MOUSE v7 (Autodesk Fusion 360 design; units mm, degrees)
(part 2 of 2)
sketch "Sketch19" plane through (0, 504.0642, 0) normal (0, 1, 0) x axis (-1, 0, 0)
  line L1 (379.7, -222.5) -> (379.7, -52.5)
  line L2 (399.8913, -222.5) -> (379.7, -222.5)
  line L3 (399.8913, -52.5) -> (399.8913, -222.5)
  line L4 (399.8913, -137.5) -> (379.7, -137.5)
  line L5 (389.7956, -133.5) -> (389.7956, -137.5)
  line L6 (389.7956, -141.5) -> (389.7956, -137.5)
  line L7 (389.7956, -149.5) -> (389.7956, -141.5)
  line L8 (389.7956, -157.5) -> (389.7956, -149.5)
  line L9 (389.7956, -165.5) -> (389.7956, -157.5)
  line L10 (389.7956, -173.5) -> (389.7956, -165.5)
  line L11 (389.7956, -181.5) -> (389.7956, -173.5)
  line L12 (389.7956, -189.5) -> (389.7956, -181.5)
  line L13 (389.7956, -197.5) -> (389.7956, -189.5)
  line L14 (389.7956, -205.5) -> (389.7956, -197.5)
  line L15 (389.7956, -213.5) -> (389.7956, -205.5)
  circle C1 centre (389.7956, -133.5) radius 2.65
  circle C2 centre (389.7956, -141.5) radius 2.5
  circle C3 centre (389.7956, -125.5) radius 2.65
  circle C4 centre (389.7956, -117.5) radius 2.65
  circle C5 centre (389.7956, -149.5) radius 2.65
  circle C6 centre (389.7956, -157.5) radius 2.65
  circle C7 centre (389.7956, -165.5) radius 2.65
  circle C8 centre (389.7956, -173.5) radius 2.65
  circle C9 centre (389.7956, -181.5) radius 2.65
  circle C10 centre (389.7956, -189.5) radius 2.65
  circle C11 centre (389.7956, -197.5) radius 2.65
  circle C12 centre (389.7956, -205.5) radius 2.65
  circle C13 centre (389.7956, -213.5) radius 2.65
  circle C14 centre (389.7956, -109.5) radius 2.65
  circle C15 centre (389.7956, -101.5) radius 2.65
  circle C16 centre (389.7956, -93.5) radius 2.65
  circle C17 centre (389.7956, -85.5) radius 2.65
  circle C18 centre (389.7956, -77.5) radius 2.65
  circle C19 centre (389.7956, -69.5) radius 2.65
  circle C20 centre (389.7956, -61.5) radius 2.65
  point P6 (379.7, -137.5)
  point P7 (399.8913, -137.5)
  point P8 (389.7956, -137.5)
  point P9 (389.7956, -133.5)
  point P10 (389.7956, -133.5)
  point P11 (389.7956, -141.5)
  point P12 (389.7956, -141.5)
  point P15 (389.7956, -141.5)
  point P16 (389.7956, -149.5)
  point P17 (389.7956, -149.5)
  point P18 (389.7956, -149.5)
  point P19 (389.7956, -157.5)
  point P20 (389.7956, -157.5)
  point P21 (389.7956, -165.5)
  point P22 (389.7956, -165.5)
  point P23 (389.7956, -165.5)
  point P24 (389.7956, -173.5)
  point P25 (389.7956, -173.5)
  point P26 (389.7956, -173.5)
  point P27 (389.7956, -181.5)
  point P28 (389.7956, -181.5)
  point P29 (389.7956, -181.5)
  point P30 (389.7956, -189.5)
  point P31 (389.7956, -189.5)
  point P32 (389.7956, -189.5)
  point P33 (389.7956, -197.5)
  point P34 (389.7956, -197.5)
  point P35 (389.7956, -197.5)
  point P36 (389.7956, -205.5)
  point P37 (389.7956, -205.5)
  point P38 (389.7956, -205.5)
  point P39 (389.7956, -213.5)
  point P40 (389.7956, -213.5)
  point P13 (389.7956, -125.5)
  point P14 (389.7956, -117.5)
  point P41 (389.7956, -109.5)
  point P42 (389.7956, -101.5)
  point P43 (389.7956, -93.5)
  point P44 (389.7956, -85.5)
  point P45 (389.7956, -77.5)
  point P46 (389.7956, -69.5)
  point P47 (389.7956, -61.5)
  midpoint L1 P6
  midpoint L3 P7
  midpoint L4 P8
  perpendicular L4 L5
  coincident P9 P10
  perpendicular L4 L6
  coincident P11 P12
  coincident P12 P15
  parallel L6 L7
  coincident P16 P17
  coincident P17 P18
  parallel L7 L8
  coincident P19 P20
  parallel L8 L9
  coincident P21 P22
  coincident P22 P23
  parallel L9 L10
  coincident P24 P25
  coincident P25 P26
  parallel L10 L11
  coincident P27 P28
  coincident P28 P29
  parallel L11 L12
  coincident P30 P31
  coincident P31 P32
  parallel L12 L13
  coincident P33 P34
  coincident P34 P35
  parallel L13 L14
  coincident P36 P37
  coincident P37 P38
  parallel L14 L15
  coincident P39 P40
  dimension "d274" distance P8 P9 = 4
  dimension "d275" diameter C1 = 5.3
  dimension "d276" distance P8 P11 = 4
  dimension "d277" diameter C2 = 5
  dimension "d278" distance P10 P13 = 8
  dimension "d279" diameter C3 = 5.3
  dimension "d280" distance P13 P14 = 8
  dimension "d281" diameter C4 = 5.3
  dimension "d282" distance P15 P16 = 8
  dimension "d283" diameter C5 = 5.3
  dimension "d284" distance P18 P19 = 8
  dimension "d285" diameter C6 = 5.3
  dimension "d286" distance P19 P21 = 8
  dimension "d287" diameter C7 = 5.3
  dimension "d288" distance P23 P24 = 8
  dimension "d289" diameter C8 = 5.3
  dimension "d290" distance P26 P27 = 8
  dimension "d291" diameter C9 = 5.3
  dimension "d292" distance P29 P30 = 8
  dimension "d293" diameter C10 = 5.3
  dimension "d294" distance P32 P33 = 8
  dimension "d295" diameter C11 = 5.3
  dimension "d296" distance P35 P36 = 8
  dimension "d297" diameter C12 = 5.3
  dimension "d298" distance P38 P39 = 8
  dimension "d299" diameter C13 = 5.3
  dimension "d300" distance P14 P41 = 8
  dimension "d301" diameter C14 = 5.3
  dimension "d302" distance P41 P42 = 8
  dimension "d303" diameter C15 = 5.3
  dimension "d304" distance P42 P43 = 8
  dimension "d305" diameter C16 = 5.3
  dimension "d306" distance P43 P44 = 8
  dimension "d307" diameter C17 = 5.3
  dimension "d308" distance P44 P45 = 8
  dimension "d309" diameter C18 = 5.3
  dimension "d310" distance P45 P46 = 8
  dimension "d311" diameter C19 = 5.3
  dimension "d312" distance P46 P47 = 8
  dimension "d313" diameter C20 = 5.3
extrude "Extrude8" add of existing geometry blind 10
extrude "Extrude9" add of existing geometry blind 10
sketch "Sketch20" plane through (0, 504.0642, 0) normal (0, 1, 0) x axis (-1, 0, 0)
  line L1 (379.7, -232.5) -> (379.7, -42.5)
  line L2 (399.8913, -232.5) -> (379.7, -232.5)
  line L3 (399.8913, -42.5) -> (399.8913, -232.5)
  line L4 (379.7, -42.5) -> (399.8913, -42.5)
  line L5 (389.7958, -45.4999) -> (389.7958, -53.4999)
  line L6 (389.795, -221.5) -> (389.795, -213.5)
  line L7 (389.795, -229.5) -> (389.795, -221.5)
  circle C1 centre (389.7958, -53.4999) radius 2.65
  circle C2 centre (389.7958, -45.4999) radius 2.65
  circle C3 centre (389.795, -221.5) radius 2.65
  circle C4 centre (389.795, -229.5) radius 2.65
  point P6 (389.7958, -53.4999)
  point P7 (389.7958, -53.4999)
  point P8 (389.7958, -45.4999)
  point P9 (389.7958, -45.4999)
  point P11 (389.795, -221.5)
  point P12 (389.795, -221.5)
  point P13 (389.795, -221.5)
  point P14 (389.795, -229.5)
  point P15 (389.795, -229.5)
  point P10 (389.795, -213.5)
  coincident P6 P7
  vertical L5
  coincident P8 P9
  vertical L6
  coincident P11 P12
  coincident P12 P13
  parallel L6 L7
  coincident P14 P15
  dimension "d319" diameter C1 = 5.3
  dimension "d320" distance P7 P8 = 8
  dimension "d321" diameter C2 = 5.3
  dimension "d322" distance P10 P11 = 8
  dimension "d323" diameter C3 = 5.3
  dimension "d324" distance P13 P14 = 8
  dimension "d325" diameter C4 = 5.3
extrude "Extrude10" cut sketch "Sketch19" + "Sketch20" profile of S1:L6 S1:C2 S1:L7 S1:C5 S1:L8 S1:C6 S1:L9 S1:C7 S1:L10 S1:C8 S1:L11 S1:C9 S1:L12 S1:C10 S1:L13 S1:C11 S1:L14 S1:C12 S1:L15 S1:C13 S2:L6 S2:C3 S2:L7 S2:C4 blind -20
extrude "Extrude11" cut of existing geometry blind -32
extrude "Extrude12" add of existing geometry blind 2
extrude "Extrude13" cut of existing geometry blind -30
work_plane "WorkPlane8" AlongDistance -97
sketch "Sketch21" plane through (0, 504.0642, 0) normal (0, 1, 0) x axis (-1, 0, 0)
  line L1 (379.7, -234.5) -> (379.7, -42.5)
  line L2 (399.8913, -234.5) -> (379.7, -234.5)
  line L3 (399.8913, -42.5) -> (399.8913, -234.5)
  line L4 (379.7, -42.5) -> (399.8913, -42.5)
  line L5 (389.7956, -137.5) -> (389.7956, -234.5)
  circle C1 centre (389.795, -229.5) radius 2.65
  circle C2 centre (389.7956, -157.5) radius 2.65
  circle C3 centre (389.7956, -189.5) radius 2.65
  circle C4 centre (389.7956, -213.5) radius 2.65
  circle C5 centre (389.7956, -181.5) radius 2.65
  circle C6 centre (389.7956, -149.5) radius 2.65
  circle C7 centre (389.7956, -165.5) radius 2.65
  circle C8 centre (389.7956, -197.5) radius 2.65
  circle C9 centre (389.7956, -205.5) radius 2.65
  circle C10 centre (389.7956, -173.5) radius 2.65
  circle C11 centre (389.7956, -141.5) radius 2.5
  circle C12 centre (389.795, -221.5) radius 2.65
  point P18 (389.7956, -234.5)
  point P19 (389.7956, -137.5)
  midpoint L2 P18
  perpendicular L2 L5
  dimension "d335" distance P18 P19 = 97
extrude "Extrude14" cut sketch "Sketch20" profile of C1 L5 C2 against normal blind 40
extrude "Extrude15" cut sketch "Sketch19" profile of C1 C3 C4 C14 C15 C16 C17 C18 C19 C20 against normal blind 25
extrude "Extrude16" add of existing geometry blind 1
extrude "Extrude17" cut of existing geometry blind -1
extrude "Extrude18" cut of existing geometry blind -7
extrude "Extrude19" cut of existing geometry blind -0.5
extrude "Extrude20" cut of existing geometry blind -7
extrude "Extrude21" cut of existing geometry blind -0.5
extrude "Extrude22" cut of existing geometry blind -5.5
sketch "Sketch13" plane through (0, 0, -202.5) normal (0, 0, -1) x axis (-1, 0, 0)
  line L1 (379.7049, 476.0642) -> (379.7049, 492.0642)
  line L2 (399.8912, 476.0642) -> (379.7049, 476.0642)
  line L3 (399.8912, 499.0642) -> (399.8912, 476.0642)
  line L4 (379.7, 499.0642) -> (399.8912, 499.0642)
  line L5 (379.7, 492.0642) -> (379.7, 499.0642)
  line L6 (379.7049, 492.0642) -> (379.7, 492.0642)
  line L7 (399.8912, 519.0178) -> (379.7, 519.0178)
  line L8 (399.8912, 517.2951) -> (399.8912, 519.0178)
  line L9 (379.7, 517.2951) -> (399.8912, 517.2951)
  line L10 (379.7, 519.0178) -> (379.7, 517.2951)
  point P10 (399.8912, 517.2951)
  point P8 (379.7, 519.0178)
  horizontal L7
  vertical L8
  horizontal L9
  vertical L10
  coincident L3 P10
  coincident L5 P8
extrude "Extrude28" add sketch "Sketch13" profile of L3 L5 L7 L8 L9 L10 along normal blind 32
sketch "Sketch14" plane through (0, 0, -72.5) normal (0, 0, 1) x axis (1, 0, 0)
  line L1 (-399.8912, 476.0642) -> (-399.8912, 499.0642)
  line L2 (-379.7049, 476.0642) -> (-399.8912, 476.0642)
  line L3 (-379.7049, 492.0642) -> (-379.7049, 476.0642)
  line L4 (-379.7, 492.0642) -> (-379.7049, 492.0642)
  line L5 (-379.7, 499.0642) -> (-379.7, 492.0642)
  line L6 (-399.8912, 499.0642) -> (-379.7, 499.0642)
  line L7 (-399.891, 519.0174) -> (-379.7, 519.0174)
  line L8 (-399.891, 516.2174) -> (-399.891, 519.0174)
  line L9 (-379.7, 516.2174) -> (-399.891, 516.2174)
  line L10 (-379.7, 519.0174) -> (-379.7, 516.2174)
  point P8 (-379.7, 519.0174)
  point P9 (-399.891, 519.0174)
  point P11 (-379.7, 516.2174)
  horizontal L7
  vertical L8
  horizontal L9
  vertical L10
  coincident L5 P8
  dimension "d356" distance P8 P9 = 20.191
  dimension "d357" distance P8 P11 = 2.8
extrude "Extrude29" add sketch "Sketch14" profile of L3 L4 L5 L7 L8 L9 L10 along normal blind 31
extrude "Extrude30" add of existing geometry blind 1.1
chamfer "Chamfer3" distance 5 Rotate Angle 80
chamfer "Chamfer4" distance 5 Rotate Angle 80
sketch "Sketch22" plane through (0, 476.0642, 0) normal (0, 1, 0) x axis (-1, 0, 0)
  line L1 (379.7049, -72.5) -> (379.7049, -100)
  line L2 (399.8912, -72.5) -> (379.7049, -72.5)
  line L3 (399.8912, -100) -> (399.8912, -72.5)
  line L4 (379.7049, -100) -> (399.8912, -100)
  line L5 (18.1656, -50) -> (430.5782, -50)
  line L6 (430.5782, -225) -> (18.1656, -225)
  line L7 (430.5782, -50) -> (430.5782, -225)
  line L8 (379.7049, -175) -> (379.7049, -202.5)
  line L9 (399.8912, -175) -> (379.7049, -175)
  line L10 (399.8912, -202.5) -> (399.8912, -175)
  line L11 (379.7049, -202.5) -> (399.8912, -202.5)
  line L12 (380, -137.5) -> (0, -137.5)
  line L13 (18.1656, -225) -> (18.1656, -50)
  circle C1 centre (190, -137.5) radius 11.2
  point P16 (190, -137.5)
  midpoint L12 P16
  dimension "d366" diameter C1 = 22.4
extrude "Extrude31" cut sketch "Sketch22" profile of L12 C1 against normal blind 30
move "Move1"
move "Move2"
work_plane "WorkPlane9" AlongDistance -20
work_plane "WorkPlane10" AlongDistance -20
sketch "Sketch23" plane through (0, 201.0642, 0) normal (0, -1, 0) x axis (-1, 0, 0)
  line L1 (-100, -75) -> (550, -75)
  line L2 (-100, 350) -> (-100, -75)
  line L3 (550, 350) -> (-100, 350)
  line L4 (550, -75) -> (550, 350)
  line L5 (225, 350) -> (225, -75)
  line L6 (550, 137.5) -> (-100, 137.5)
  line L7 (532.3496, 332.2603) -> (-82.3496, -57.2603)
  line L8 (-82.3496, 332.2603) -> (532.3496, -57.2603)
  line L9 (550, -75) -> (-100, -75)
  line L10 (550, 350) -> (550, -75)
  line L11 (-100, 350) -> (550, 350)
  line L12 (-100, -75) -> (-100, 350)
  line L13 (550, 350) -> (-100, -75)
  line L14 (-100, 350) -> (550, -75)
  line L15 (532.3496, 332.2603) -> (-82.3496, -57.2603)
  line L16 (-82.3496, 332.2603) -> (532.3496, -57.2603)
  line L17 (-89.6979, 343.264) -> (539.6979, 343.264)
  line L18 (-89.6979, -68.264) -> (-89.6979, 343.264)
  line L19 (539.6979, -68.264) -> (-89.6979, -68.264)
  line L20 (539.6979, 343.264) -> (539.6979, -68.264)
  line L21 (-89.6979, -68.264) -> (539.6979, 343.264)
  line L22 (539.6979, -68.264) -> (-89.6979, 343.264)
  point P6 (225, -75)
  point P7 (225, 350)
  point P8 (-100, 137.5)
  point P9 (550, 137.5)
  point P14 (225, 137.5)
  point P18 (225, 137.5)
  point P22 (225, 137.5)
  point P27 (225, 137.5)
  point P23 (539.6979, 343.264)
  horizontal L1
  perpendicular L1 L2
  perpendicular L2 L3
  perpendicular L1 L4
  midpoint L1 P6
  midpoint L3 P7
  midpoint L2 P8
  midpoint L4 P9
  coincident L7 P14
  coincident L8 P14
  midpoint L5 P14
  horizontal L9
  perpendicular L9 L10
  parallel L9 L11
  parallel L10 L12
  coincident L13 P18
  coincident L14 P18
  coincident P14 P18
  coincident L15 P22
  coincident L16 P22
  coincident P14 P22
  horizontal L17
  perpendicular L17 L18
  parallel L17 L19
  parallel L18 L20
  coincident L21 P27
  coincident L22 P27
  coincident L13 P23
  coincident P22 P27
extrude "Extrude32" cut sketch "Sketch23" profile of L1 L2 L3 L4 L5 L6 L9 L10 L11 L12 L17 L18 L19 L20 against normal blind 75
fillet "Fillet2" radius 27
fillet "Fillet3" radius 27
fillet "Fillet4" radius 30
fillet "Fillet5" radius 30
sketch "Sketch24" plane through (0, 168.5642, 0) normal (0, 1, 0) x axis (-1, 0, 0)
  line L1 (546, -350.953) -> (-96, -350.953)
  line L2 (550, 70.047) -> (550, -346.953)
  line L3 (-96, 74.047) -> (546, 74.047)
  line L4 (-100, -346.953) -> (-100, 70.047)
  line L5 (-62.5, 36.547) -> (-62.5, -313.453)
  line L6 (512.5, 36.547) -> (-62.5, 36.547)
  line L7 (512.5, -313.453) -> (512.5, 36.547)
  line L8 (-62.5, -313.453) -> (512.5, -313.453)
  arc A1 centre (530.6642, -331.6172) radius 7.5 clockwise from (525.5655, -337.1175) to (536.3487, -326.7247)
  arc A2 centre (531.25, -332.225) radius 7.5 clockwise from (525.5655, -337.1175) to (536.3487, -326.7247)
  arc A3 centre (-81.25, -332.225) radius 7.5 clockwise from (-86.3488, -326.7248) to (-75.5655, -337.1174)
  arc A4 centre (-80.6642, -331.6172) radius 7.5 clockwise from (-86.3488, -326.7248) to (-75.5655, -337.1174)
  arc A5 centre (-81.25, 55.25) radius 7.5 clockwise from (-75.8871, 60.4931) to (-86.0271, 49.4682)
  arc A6 centre (-80.6642, 54.7112) radius 7.5 clockwise from (-75.8871, 60.4931) to (-86.0271, 49.4682)
  arc A7 centre (-96, -346.953) radius 4 clockwise from (-96, -350.953) to (-100, -346.953)
  arc A8 centre (546, -346.953) radius 4 clockwise from (550, -346.953) to (546, -350.953)
  arc A9 centre (546, 70.047) radius 4 clockwise from (546, 74.047) to (550, 70.047)
  arc A10 centre (-96, 70.047) radius 4 clockwise from (-100, 70.047) to (-96, 74.047)
  arc A11 centre (530.6642, 54.7112) radius 7.5 clockwise from (536.0271, 49.4681) to (525.8872, 60.4931)
  arc A12 centre (531.25, 55.25) radius 7.5 clockwise from (536.0271, 49.4681) to (525.8872, 60.4931)
  circle C1 centre (-80.6642, 54.7112) radius 7.5
  circle C2 centre (-80.6642, 54.7112) radius 7.5
  concentric A6 C1
  concentric C1 C2
extrude "Extrude28" add sketch "Sketch24" profile of A5 C1 C2 along normal blind 15
sketch "Sketch25" plane through (0, 168.5642, 0) normal (0, 1, 0) x axis (-1, 0, 0)
  line L1 (546, -350.953) -> (-96, -350.953)
  line L2 (550, 70.047) -> (550, -346.953)
  line L3 (-96, 74.047) -> (546, 74.047)
  line L4 (-100, -346.953) -> (-100, 70.047)
  line L5 (-62.5, 36.547) -> (-62.5, -313.453)
  line L6 (512.5, 36.547) -> (-62.5, 36.547)
  line L7 (512.5, -313.453) -> (512.5, 36.547)
  line L8 (-62.5, -313.453) -> (512.5, -313.453)
  circle C1 centre (-80.6642, 54.7112) radius 7.5
  arc A1 centre (530.6642, -331.6172) radius 7.5 clockwise from (525.5655, -337.1175) to (536.3487, -326.7247)
  arc A2 centre (531.25, -332.225) radius 7.5 clockwise from (525.5655, -337.1175) to (536.3487, -326.7247)
  arc A3 centre (-81.25, -332.225) radius 7.5 clockwise from (-86.3488, -326.7248) to (-75.5655, -337.1174)
  arc A4 centre (-80.6642, -331.6172) radius 7.5 clockwise from (-86.3488, -326.7248) to (-75.5655, -337.1174)
  arc A5 centre (-96, -346.953) radius 4 clockwise from (-96, -350.953) to (-100, -346.953)
  arc A6 centre (546, -346.953) radius 4 clockwise from (550, -346.953) to (546, -350.953)
  arc A7 centre (546, 70.047) radius 4 clockwise from (546, 74.047) to (550, 70.047)
  arc A8 centre (-96, 70.047) radius 4 clockwise from (-100, 70.047) to (-96, 74.047)
  arc A9 centre (530.6642, 54.7112) radius 7.5 clockwise from (536.0271, 49.4681) to (525.8872, 60.4931)
  arc A10 centre (531.25, 55.25) radius 7.5 clockwise from (536.0271, 49.4681) to (525.8872, 60.4931)
  circle C2 centre (-80.6642, -331.6172) radius 7.5
  concentric A4 C2
extrude "Extrude29" add sketch "Sketch25" profile of A3 C2 along normal blind 15
sketch "Sketch26" plane through (0, 168.5642, 0) normal (0, 1, 0) x axis (-1, 0, 0)
  line L1 (546, -350.953) -> (-96, -350.953)
  line L2 (550, 70.047) -> (550, -346.953)
  line L3 (-96, 74.047) -> (546, 74.047)
  line L4 (-100, -346.953) -> (-100, 70.047)
  line L5 (-62.5, 36.547) -> (-62.5, -313.453)
  line L6 (512.5, 36.547) -> (-62.5, 36.547)
  line L7 (512.5, -313.453) -> (512.5, 36.547)
  line L8 (-62.5, -313.453) -> (512.5, -313.453)
  circle C1 centre (-80.6642, -331.6172) radius 7.5
  circle C2 centre (-80.6642, 54.7112) radius 7.5
  arc A1 centre (530.6642, -331.6172) radius 7.5 clockwise from (525.5655, -337.1175) to (536.3487, -326.7247)
  arc A2 centre (531.25, -332.225) radius 7.5 clockwise from (525.5655, -337.1175) to (536.3487, -326.7247)
  arc A3 centre (-96, -346.953) radius 4 clockwise from (-96, -350.953) to (-100, -346.953)
  arc A4 centre (546, -346.953) radius 4 clockwise from (550, -346.953) to (546, -350.953)
  arc A5 centre (546, 70.047) radius 4 clockwise from (546, 74.047) to (550, 70.047)
  arc A6 centre (-96, 70.047) radius 4 clockwise from (-100, 70.047) to (-96, 74.047)
  arc A7 centre (530.6642, 54.7112) radius 7.5 clockwise from (536.0271, 49.4681) to (525.8872, 60.4931)
  arc A8 centre (531.25, 55.25) radius 7.5 clockwise from (536.0271, 49.4681) to (525.8872, 60.4931)
  circle C3 centre (531.25, 55.25) radius 8.0664
  concentric A8 C3
extrude "Extrude30" add sketch "Sketch26" profile of A7 A8 C3 along normal blind 15
sketch "Sketch27" plane through (0, 168.5642, 0) normal (0, 1, 0) x axis (-1, 0, 0)
  line L1 (546, -350.953) -> (-96, -350.953)
  line L2 (550, 70.047) -> (550, -346.953)
  line L3 (-96, 74.047) -> (546, 74.047)
  line L4 (-100, -346.953) -> (-100, 70.047)
  line L5 (-62.5, 36.547) -> (-62.5, -313.453)
  line L6 (512.5, 36.547) -> (-62.5, 36.547)
  line L7 (512.5, -313.453) -> (512.5, 36.547)
  line L8 (-62.5, -313.453) -> (512.5, -313.453)
  arc A1 centre (531.25, 55.25) radius 8.0664 clockwise from (523.1836, 55.25) to (530.5766, 47.2117)
  arc A2 centre (530.6642, 54.7112) radius 7.5 clockwise from (530.5766, 47.2117) to (523.1836, 55.25)
  circle C1 centre (-80.6642, -331.6172) radius 7.5
  circle C2 centre (-80.6642, 54.7112) radius 7.5
  arc A3 centre (530.6642, -331.6172) radius 7.5 clockwise from (525.5655, -337.1175) to (536.3487, -326.7247)
  arc A4 centre (531.25, -332.225) radius 7.5 clockwise from (525.5655, -337.1175) to (536.3487, -326.7247)
  arc A5 centre (-96, -346.953) radius 4 clockwise from (-96, -350.953) to (-100, -346.953)
  arc A6 centre (546, -346.953) radius 4 clockwise from (550, -346.953) to (546, -350.953)
  arc A7 centre (546, 70.047) radius 4 clockwise from (546, 74.047) to (550, 70.047)
  arc A8 centre (-96, 70.047) radius 4 clockwise from (-100, 70.047) to (-96, 74.047)
  circle C3 centre (531.25, -332.225) radius 8.2898
  concentric A4 C3
extrude "Extrude31" add sketch "Sketch27" profile of A3 A4 C3 along normal blind 15
sketch "Sketch28" plane through (0, 476.0642, 0) normal (0, 1, 0) x axis (-1, 0, 0)
  line L1 (379.7049, -72.5) -> (379.7049, -100)
  line L2 (399.8912, -72.5) -> (379.7049, -72.5)
  line L3 (399.8912, -100) -> (399.8912, -72.5)
  line L4 (379.7049, -100) -> (399.8912, -100)
  line L5 (18.1656, -50) -> (430.5782, -50)
  line L6 (18.1656, -225) -> (18.1656, -50)
  line L7 (430.5782, -225) -> (18.1656, -225)
  line L8 (430.5782, -50) -> (430.5782, -225)
  line L9 (379.7049, -175) -> (379.7049, -202.5)
  line L10 (399.8912, -175) -> (379.7049, -175)
  line L11 (399.8912, -202.5) -> (399.8912, -175)
  line L12 (379.7049, -202.5) -> (399.8912, -202.5)
  circle C1 centre (190, -137.5) radius 11.2
  circle C2 centre (190, -137.5) radius 14.5
  concentric C1 C2
  dimension "d389" diameter C2 = 29
extrude "Extrude33" cut sketch "Sketch28" profile of C1 C2 against normal blind 20
sketch "Sketch29" plane through (0, 476.0642, 0) normal (0, 1, 0) x axis (-1, 0, 0)
  line L1 (379.7049, -72.5) -> (379.7049, -100)
  line L2 (399.8912, -72.5) -> (379.7049, -72.5)
  line L3 (399.8912, -100) -> (399.8912, -72.5)
  line L4 (379.7049, -100) -> (399.8912, -100)
  line L5 (18.1656, -50) -> (430.5782, -50)
  line L6 (18.1656, -225) -> (18.1656, -50)
  line L7 (430.5782, -225) -> (18.1656, -225)
  line L8 (430.5782, -50) -> (430.5782, -225)
  line L9 (379.7049, -175) -> (379.7049, -202.5)
  line L10 (399.8912, -175) -> (379.7049, -175)
  line L11 (399.8912, -202.5) -> (399.8912, -175)
  line L12 (379.7049, -202.5) -> (399.8912, -202.5)
  line L13 (173.3434, -130.2) -> (173.3434, -137.5)
  line L14 (173.3434, -144.8) -> (173.3434, -137.5)
  line L15 (167.5, -137.5) -> (175.5, -137.5)
  line L16 (167.5, -130) -> (167.5, -137.5)
  line L17 (177.5903, -130) -> (167.5, -130)
  line L18 (167.5, -145) -> (167.5, -137.5)
  line L19 (177.5903, -145) -> (167.5, -145)
  circle C1 centre (190, -137.5) radius 14.5
  point P18 (175.5, -137.5)
  point P21 (177.5903, -130)
  point P23 (177.5903, -145)
  point P15 (173.3434, -137.5)
  point P16 (173.3434, -130.2)
  point P17 (173.3434, -144.8)
  point P19 (167.5, -137.5)
  vertical L13
  parallel L13 L14
  coincident C1 P18
  perpendicular L13 L15
  perpendicular L15 L16
  coincident C1 P21
  perpendicular L16 L17
  perpendicular L15 L18
  coincident C1 P23
  perpendicular L16 L19
  dimension "d392" distance P15 P16 = 7.3
  dimension "d393" distance P15 P17 = 7.3
  dimension "d394" distance P18 P19 = 8
extrude "Extrude34" cut sketch "Sketch29" profile of C1 L15 L16 L17 L18 L19 against normal blind 21
work_plane "WorkPlane11" AlongDistance -325 (= "-650.00 mm / 2")
mirror "Mirror1" mirrorStitchTolerance 0.1
mirror "Mirror2" mirrorStitchTolerance 0.1
sketch "Sketch30" plane through (0, 476.0642, 0) normal (0, 1, 0) x axis (-1, 0, 0)
  line L1 (379.7049, -175) -> (379.7049, -202.5)
  line L2 (399.8912, -175) -> (379.7049, -175)
  line L3 (399.8912, -202.5) -> (399.8912, -175)
  line L4 (379.7049, -202.5) -> (399.8912, -202.5)
  line L5 (18.1656, -50) -> (430.5782, -50)
  line L6 (18.1656, -225) -> (18.1656, -50)
  line L7 (430.5782, -225) -> (18.1656, -225)
  line L8 (430.5782, -50) -> (430.5782, -225)
  line L9 (379.7049, -72.5) -> (379.7049, -100)
  line L10 (399.8912, -72.5) -> (379.7049, -72.5)
  line L11 (399.8912, -100) -> (399.8912, -72.5)
  line L12 (379.7049, -100) -> (399.8912, -100)
  line L13 (167.5, -145) -> (177.5903, -145)
  line L14 (167.5, -130) -> (167.5, -145)
  line L15 (177.5903, -130) -> (167.5, -130)
  line L16 (272.4, -145) -> (282.5, -145)
  line L17 (272.421, -130) -> (282.5, -130)
  line L18 (272.4, -145) -> (272.421, -130)
  line L19 (282.5, -145) -> (282.5, -130)
  line L20 (237.6187, -137.5) -> (282.5, -137.5)
  arc A1 centre (190, -137.5) radius 14.5 clockwise from (177.5903, -130) to (177.5903, -145)
  circle C1 centre (260.0593, -137.5) radius 14.3757
  point P23 (282.5, -137.5)
  point P25 (260.0593, -137.5)
  horizontal L16
  horizontal L17
  perpendicular L16 L19
  midpoint L19 P23
  perpendicular L19 L20
  midpoint L20 P25
extrude "Extrude35" cut sketch "Sketch30" profile of L16 L17 L18 L19 L20 C1 against normal blind 19
extrude "Extrude36" add of existing geometry blind 329.6
extrude "Extrude37" cut of existing geometry blind -50
extrude "Extrude38" cut of existing geometry blind -40
extrude "Extrude39" add of existing geometry blind 10
extrude "Extrude40" add of existing geometry blind 10
extrude "Extrude41" add of existing geometry blind 130
work_plane "WorkPlane12" AlongDistance 0
extrude "Extrude42" cut of existing geometry blind -135
work_plane "WorkPlane1" AlongDistance 0
sketch "Sketch1" plane through (0, 476.0642, 0) normal (0, 1, 0) x axis (1, 0, 0)
  line L1 (-259.9225, 123) -> (-259.9225, 151.875)
  line L2 (-273, 137.5) -> (-245.7, 137.5)
  circle C1 centre (-259.9225, 137.4375) radius 14.4375
  circle C2 centre (-259.9225, 137.4375) radius 6
  point P6 (-259.9225, 137.4375)
  point P3 (-259.9225, 123)
  vertical L1
  horizontal L2
  midpoint L1 P6
  coincident P3 C1
  concentric C1 C2
  dimension "d420" diameter C2 = 12
extrude "Extrude1" new body sketch "Sketch1" profile of L1 L2 C2 along normal blind 50
sketch "Sketch2" plane through (0, 526.0642, 0) normal (0, 1, 0) x axis (-1, 0, 0)
  circle C1 centre (259.9225, -137.4375) radius 6
  circle C2 centre (259.9225, -137.4375) radius 7.8396
  concentric C1 C2
extrude "Extrude2" add sketch "Sketch2" against normal blind 56
sketch "Sketch31" plane through (-379.7, 0, 0) normal (1, 0, 0) x axis (0, 0, -1)
  line L1 (234.5, 494.0642) -> (41.5, 494.0642)
  line L2 (234.5, 504.0642) -> (234.5, 494.0642)
  line L3 (41.5, 504.0642) -> (234.5, 504.0642)
  line L4 (41.5, 494.0642) -> (41.5, 504.0642)
  line L5 (202.5, 499) -> (202.5, 494)
  line L6 (72.5, 499) -> (202.5, 499)
  line L7 (72.5, 494.0642) -> (72.5, 499)
  line L8 (202.5, 494) -> (72.5, 494.0642)
  point P9 (72.5, 494.0642)
  perpendicular L1 L5
  perpendicular L5 L6
  coincident L1 P9
  perpendicular L1 L7
extrude "Extrude23" cut sketch "Sketch31" profile of L1 L5 L6 L7 against normal blind 80
extrude "Extrude24" add of existing geometry blind 15
extrude "Extrude25" cut of existing geometry blind -15
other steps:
extrude "Extrude2" cut sketch "Sketch15" profile of L2 L5 L7 L8 L9 L10 L11 L12 L13 L14 along normal blind 7.8
extrude "Extrude2" cut sketch "Sketch2" profile of L9 L10 C1 against normal blind 20
extrude "Extrude4" cut sketch "Sketch4" profile of L9 L10 C1 against normal blind 20
extrude "Extrude6" cut sketch "Sketch6" profile of L9 C1 against normal blind 20
extrude "Extrude8" cut sketch "Sketch8" profile of L9 C1 against normal blind 20
create_component "CreateComponent1"
create_component "CreateComponent2"
create_component "CreateComponent3"
create_component "CreateComponent4"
